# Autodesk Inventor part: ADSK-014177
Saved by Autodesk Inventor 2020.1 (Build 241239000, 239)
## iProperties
Part Number: ADSK-014177
Material: Allgemein
Description: Framegenerator-Skeleton-Referenz
Document SubType Name: Modellieren
Designer: lutzd
Density: 1 g/cm^3
Appearance: Vorgabe
_SkeletonDoc: Frame Skeleton File
_Version: 15.0.0
DocNumber: ADSK-014177
Folder: .
Dimensions: 0x0x0 mm
Mass: 0 kg
Title: Gestellrahmenbauteil(e)
Author: lutzd
Revision Number: -
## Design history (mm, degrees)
sketch "Referenzrahmen"
node "Volumenkörper"
node "Flächenkörper"
